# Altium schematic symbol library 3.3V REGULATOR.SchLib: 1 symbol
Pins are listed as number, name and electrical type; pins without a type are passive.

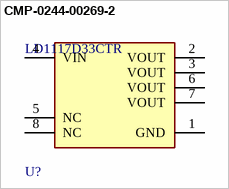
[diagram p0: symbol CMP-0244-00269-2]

## CMP-0244-00269-2
designator U?, comment LD1117D33CTR
IC REG LINEAR 3.3V 800MA 8SO; Accuracy: 1%; Max Input Voltage: 15V; Quiescent Current: 10mA; Number of Regulators: 1; Output Current: 1.3A; Max Power Dissipation: 12W; Output Type: Fixed; Input Bias Current: 5mA; Dropout Voltage: 1.1V; Polarity: Positive
footprint FP-SO-8-0016023-IPC_C
footprint FP-SO-8-0016023-IPC_B
footprint FP-SO-8-0016023-MFG
footprint FP-SO-8-0016023-IPC_A
pins: 1 GND (power), 2 VOUT (power), 3 VOUT (power), 4 VIN (power), 5 NC, 6 VOUT (power), 7 VOUT (power), 8 NC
